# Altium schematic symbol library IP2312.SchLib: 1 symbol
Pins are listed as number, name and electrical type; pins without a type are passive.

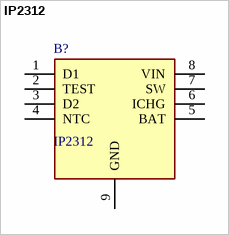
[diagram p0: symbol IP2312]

## IP2312
designator B?
ESOP-8L DC-DC Converters RoHS; Manufacturer_Name: INJOINIC; Geometry.Height: 1.65mm
footprint SOIC127P600X165-9N
pins: 1 D1, 2 TEST, 3 D2, 4 NTC, 5 BAT, 6 ICHG, 7 SW, 8 VIN, 9 GND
